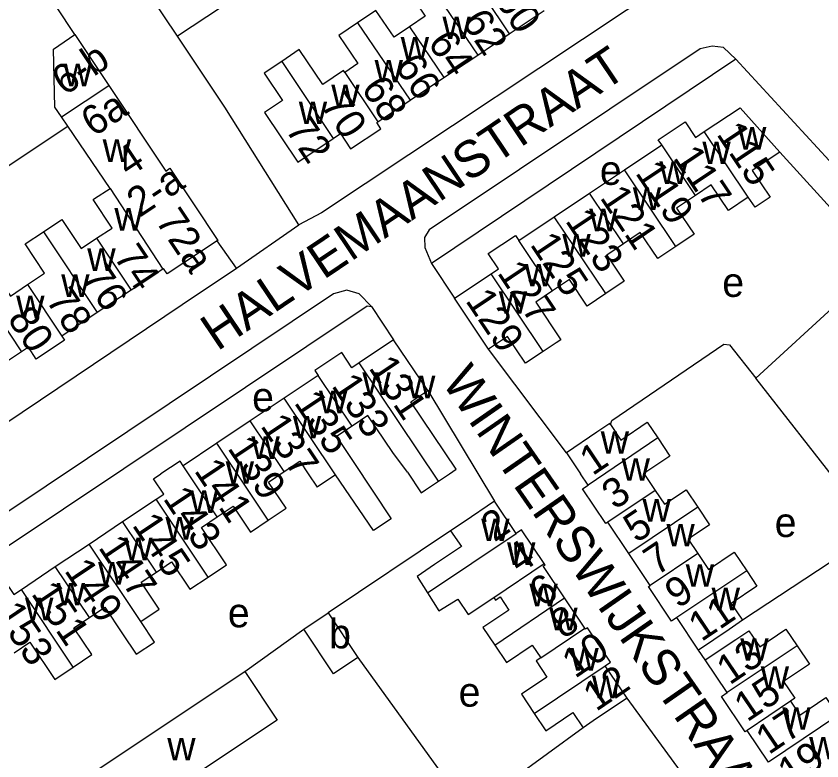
# Model space of a CAD drawing. Extents: x 158356 to 159894, y 383831 to 385260.
# Drawn here: x 158884.2 to 158994, y 384210.9 to 384312.4 of the extents above; entities that cross this region are included whole.
import ezdxf

# ---------------------------------------------------------------- set-up
doc = ezdxf.new("R2010")
doc.units = 0
for name, color, linetype in [('BLT_Basislijn', 7, 'Continuous'), ('BLT_Bebouwing', 7, 'Continuous'), ('BLT_Centroide', 7, 'Continuous'), ('BLT_Huisnummer', 7, 'Continuous'), ('BLT_Huisnummer_ tussenligend', 7, 'Continuous'), ('BLT_Huisnummer_reeks', 7, 'Continuous'), ('BLT_Onderverdeling_panden', 7, 'Continuous'), ('BLT_Straatnaam', 7, 'Continuous'), ('BLT_Vlakafsluiter', 7, 'Continuous')]:
    doc.layers.add(name, color=color, linetype=linetype)

msp = doc.modelspace()

# ---------------------------------------------------------------- linework, layer by layer
at = {"layer": 'BLT_Basislijn'}
for p, q in [((158924.95, 384322.07), (158906.15, 384309.68)), ((159022.47, 384262.77), (158982.28, 384306.54)), ((158988.24, 384293.86), (159002.07, 384278.66)), ((158984.98, 384263.05), (158996.47, 384273.59)), ((158959.16, 384252.88), (158948.56, 384267.02)), ((159001.46, 384241.95), (158984.98, 384263.05)), ((158940.26, 384261.37), (158949.37, 384246.27)), ((158943.39, 384242.25), (158926.68, 384231.06)), ((158915.33, 384223.05), (158923.36, 384228.85)), ((158978.09, 384224.66), (158977.18, 384226)), ((158930.73, 384224.98), (158945.89, 384204.06)), ((158979.18, 384203.45), (158967.44, 384219.43)), ((158961.44, 384215.4), (158945.89, 384204.06))]:
    msp.add_line(p, q, dxfattribs=at)
for points in [[(158959.61, 384341.76), (158973.75, 384319.75), (158974.01, 384318.23), (158973.25, 384317.18), (158925.8, 384285.6), (158922.7, 384283.94)], [(158906.15, 384309.68), (158889.77, 384334.13)], [(158892.18, 384309.89), (158882.19, 384325.03), (158881.31, 384325.78), (158873.9, 384320.84)], [(158922.7, 384283.94), (158912.61, 384300), (158906.15, 384309.68)], [(158982.28, 384306.54), (158980.6, 384308.12), (158979.04, 384308.32), (158977.39, 384307.96), (158940.44, 384283.26), (158939.81, 384282.23), (158939.86, 384280.87), (158940.8, 384278.67)], [(158982.28, 384306.54), (158940.8, 384278.67)], [(158797.78, 384244.29), (158799.68, 384245.48), (158809.98, 384243.39), (158891.2, 384297.39)], [(158914.2, 384278.07), (158911.56, 384281.79)], [(158812.32, 384215.48), (158814.95, 384211.31), (158906.8, 384273.1), (158914.2, 384278.07)], [(158940.8, 384278.67), (158943.92, 384273.95)], [(158932.59, 384272.84), (158930.9, 384274.57), (158929.22, 384275.07), (158927.41, 384274.56), (158849.03, 384222.1), (158848.3, 384220.88), (158848.42, 384219.19), (158849.2, 384217.57)], [(158849.2, 384217.57), (158932, 384272.92), (158932.59, 384272.84)], [(158932.59, 384272.84), (158935.62, 384268.3)], [(158965.16, 384256.75), (158965.34, 384257.27), (158980.61, 384267.7), (158981.38, 384267.6), (158984.98, 384263.05)], [(159001.46, 384241.95), (159000.15, 384241.24), (158983.15, 384230.05)]]:
    msp.add_lwpolyline(points, dxfattribs=at)
at = {"layer": 'BLT_Bebouwing'}
for p, q in [((158951.37, 384309.97), (158956.15, 384313.15)), ((158947.09, 384307.1), (158951.37, 384309.97)), ((158942.47, 384304.02), (158947.09, 384307.1)), ((158937.86, 384300.94), (158942.47, 384304.02)), ((158891.2, 384297.39), (158890.35, 384298.66)), ((158896.99, 384288.89), (158891.2, 384297.39)), ((158967.09, 384291.47), (158972.16, 384294.86)), ((158962.33, 384288.28), (158967.09, 384291.47)), ((158957.51, 384285.05), (158962.33, 384288.28)), ((158952.69, 384281.82), (158957.51, 384285.05)), ((158904.14, 384277.93), (158899.83, 384275.07)), ((158943.92, 384273.95), (158948.91, 384277.29)), ((158899.83, 384275.07), (158895.22, 384272)), ((158948.56, 384267.02), (158943.92, 384273.95)), ((158895.22, 384272), (158890.39, 384268.78)), ((158935.62, 384268.3), (158930.91, 384265.15)), ((158940.26, 384261.37), (158935.62, 384268.3)), ((158884.89, 384266.64), (158879.82, 384263.27)), ((158925.35, 384263.43), (158920.7, 384260.32)), ((158920.7, 384260.32), (158916.07, 384257.22)), ((158916.07, 384257.22), (158911.52, 384254.18)), ((158911.52, 384254.18), (158906.93, 384251.11)), ((158959.16, 384252.88), (158961.1, 384250.01)), ((158918.56, 384248.89), (158920.69, 384250.32)), ((158923.99, 384250), (158925.19, 384248.21)), ((158927.68, 384249.88), (158925.19, 384248.21)), ((158941.72, 384249.01), (158943.24, 384250.03)), ((158962.12, 384248.48), (158961.1, 384250.01)), ((158969.73, 384250.04), (158971.27, 384247.76)), ((158898.68, 384243.5), (158903.24, 384246.55)), ((158952.31, 384241.89), (158949.37, 384246.27)), ((158894.1, 384240.44), (158898.68, 384243.5)), ((158967.69, 384239.14), (158964.81, 384243.42)), ((158889.5, 384237.36), (158894.1, 384240.44)), ((158970.6, 384234.81), (158967.69, 384239.14)), ((158884.88, 384234.26), (158889.5, 384237.36)), ((158958.93, 384233.09), (158956.12, 384237.26)), ((158961.69, 384228.98), (158958.93, 384233.09)), ((158923.36, 384228.85), (158926.68, 384231.06)), ((158926.68, 384231.06), (158930.73, 384224.98)), ((158977.18, 384226), (158974.21, 384230.41)), ((158981.09, 384220.2), (158978.09, 384224.66)), ((158889.79, 384206.08), (158915.33, 384223.05)), ((158967.44, 384219.43), (158964.47, 384223.85)), ((158986.7, 384210.73), (158983.81, 384215.04))]:
    msp.add_line(p, q, dxfattribs=at)
for points in [[(158939.93, 384317.73), (158937.46, 384316.07), (158939.93, 384312.4), (158937.8, 384310.96)], [(158937.8, 384310.96), (158935.67, 384309.53), (158933.21, 384313.18), (158930.69, 384311.47)], [(158930.69, 384311.47), (158928.17, 384309.76), (158930.74, 384305.94), (158928.95, 384304.74)], [(158890.35, 384298.66), (158889.46, 384300), (158889.25, 384307.92), (158892.18, 384309.89)], [(158892.18, 384309.89), (158896.8, 384302.95)], [(158928.95, 384304.74), (158928.78, 384304.99), (158925.95, 384303.1), (158922.76, 384307.84), (158922.14, 384307.43), (158920.37, 384306.24)], [(158920.37, 384306.24), (158917.98, 384304.65), (158920.47, 384300.92), (158919.09, 384300), (158918.03, 384299.29), (158922.56, 384292.5), (158927.39, 384295.73)], [(158896.8, 384302.95), (158904.55, 384291.29), (158905.1, 384291.66), (158911.64, 384281.84), (158911.56, 384281.79)], [(158933.45, 384297.99), (158936.46, 384300), (158937.86, 384300.94)], [(158977.96, 384296.67), (158982.83, 384299.92), (158988.24, 384293.86)], [(158927.39, 384295.73), (158928.38, 384296.39), (158929.76, 384294.31), (158933.87, 384297.06), (158933.31, 384297.9), (158933.45, 384297.99)], [(158972.16, 384294.86), (158971.69, 384295.56), (158975.35, 384298.01), (158976.77, 384295.87), (158977.96, 384296.67)], [(158988.24, 384293.86), (158984.49, 384291.35), (158986.93, 384287.72), (158984.88, 384286.35), (158983.95, 384287.73)], [(158895.14, 384282.12), (158897.25, 384283.52), (158894.66, 384287.42), (158894.86, 384287.55), (158896.99, 384288.89)], [(158983.95, 384287.73), (158981.24, 384285.92), (158978.92, 384289.39), (158976.78, 384287.96)], [(158976.78, 384287.96), (158974.19, 384286.23), (158976.57, 384282.67), (158974.09, 384281.01)], [(158887.9, 384283.01), (158890.4, 384284.68), (158893.03, 384280.72), (158895.14, 384282.12)], [(158885.72, 384275.8), (158888.05, 384277.35), (158885.39, 384281.35), (158887.9, 384283.01)], [(158948.91, 384277.29), (158949.91, 384277.96), (158948.52, 384280.04), (158952.22, 384282.52), (158952.69, 384281.82)], [(158974.09, 384281.01), (158971.62, 384279.35), (158969.24, 384282.89), (158966.96, 384281.36)], [(158911.56, 384281.79), (158904.76, 384277.27), (158904.27, 384278.02), (158904.14, 384277.93)], [(158966.96, 384281.36), (158964.68, 384279.83), (158967.06, 384276.27), (158964.53, 384274.58)], [(158877.59, 384277.6), (158880.06, 384279.24), (158883.39, 384274.25), (158885.72, 384275.8)], [(158964.53, 384274.58), (158962, 384272.88), (158959.58, 384276.49), (158957.28, 384274.95)], [(158957.28, 384274.95), (158954.99, 384273.42), (158958.41, 384268.3), (158957.75, 384267.86), (158956, 384266.69)], [(158890.39, 384268.78), (158890.76, 384268.22), (158886.9, 384265.66), (158885.83, 384267.27), (158884.89, 384266.64)], [(158956, 384266.69), (158953.59, 384265.08), (158951.14, 384268.74), (158948.56, 384267.02)], [(158930.91, 384265.15), (158929.92, 384264.48), (158928.54, 384266.54), (158924.9, 384264.1), (158925.35, 384263.43)], [(158943.24, 384250.03), (158944.14, 384250.63), (158937.98, 384259.84), (158940.26, 384261.37)], [(158937.5, 384250.25), (158935.5, 384252.91), (158932.12, 384257.96), (158929.97, 384256.52)], [(158965.16, 384256.75), (158966.59, 384254.62), (158970.17, 384257.04), (158971.62, 384254.9)], [(158929.97, 384256.52), (158927.82, 384255.09), (158930.18, 384251.55), (158935.3, 384243.9), (158932.88, 384242.28), (158927.68, 384249.88)], [(158965.16, 384256.75), (158965.07, 384256.87), (158963.3, 384255.68), (158959.16, 384252.88)], [(158971.62, 384254.9), (158973.28, 384252.44), (158969.73, 384250.04)], [(158906.93, 384251.11), (158906.51, 384251.75), (158903.89, 384250)], [(158920.69, 384250.32), (158922.82, 384251.74), (158923.99, 384250)], [(158903.24, 384246.55), (158904.28, 384247.25), (158902.89, 384249.33), (158903.89, 384250)], [(158937.5, 384250.25), (158939.38, 384247.44), (158939.98, 384247.85), (158941.72, 384249.01)], [(158918.53, 384243.7), (158920.95, 384245.32), (158918.56, 384248.89)], [(158964.81, 384243.42), (158964.52, 384243.23), (158961.35, 384247.96), (158962.12, 384248.48)], [(158971.27, 384247.76), (158972.54, 384245.86), (158975.49, 384247.84), (158977.09, 384245.46)], [(158949.37, 384246.27), (158945.21, 384243.48), (158943.39, 384242.25)], [(158911.58, 384244.16), (158913.75, 384245.61), (158916.12, 384242.08), (158918.53, 384243.7)], [(158977.09, 384245.46), (158978.69, 384243.08), (158975.76, 384241.11), (158977.07, 384239.16)], [(158910.35, 384235.93), (158912.84, 384237.6), (158909.42, 384242.71), (158911.58, 384244.16)], [(158943.39, 384242.25), (158944.85, 384240.09), (158941.2, 384237.64), (158938.83, 384236.04), (158940.24, 384233.78)], [(158956.15, 384237.78), (158953.05, 384242.39), (158952.31, 384241.89)], [(158977.07, 384239.16), (158978.53, 384236.99), (158982.03, 384239.35), (158983.74, 384236.81)], [(158903.29, 384236.62), (158905.36, 384238.01), (158907.86, 384234.27), (158910.35, 384235.93)], [(158956.12, 384237.26), (158956, 384237.44), (158956.26, 384237.61), (158956.15, 384237.78)], [(158901.18, 384229.87), (158903.68, 384231.55), (158901.21, 384235.23), (158903.29, 384236.62)], [(158983.74, 384236.81), (158985.14, 384234.72), (158981.61, 384232.34), (158983.15, 384230.05)], [(158879.22, 384232.59), (158878.8, 384233.22), (158882.46, 384235.67), (158883.86, 384233.58), (158884.88, 384234.26)], [(158974.21, 384230.41), (158973.51, 384229.93), (158970.35, 384234.64), (158970.6, 384234.81)], [(158940.24, 384233.78), (158941.78, 384231.32), (158944.36, 384232.93), (158945.78, 384230.82), (158949.26, 384233.15)], [(158950.12, 384233.23), (158951.33, 384231.43), (158947.79, 384229.05), (158949.39, 384226.68)], [(158949.26, 384233.15), (158949.49, 384232.8), (158950.12, 384233.23)], [(158894.15, 384230.42), (158896.24, 384231.82), (158898.67, 384228.19), (158900.52, 384225.43), (158903.01, 384227.09), (158901.18, 384229.87)], [(158891.96, 384223.67), (158894.5, 384225.37), (158892.05, 384229.02), (158894.15, 384230.42)], [(158983.15, 384230.05), (158981.33, 384228.79), (158977.18, 384226)], [(158930.73, 384224.98), (158927.41, 384222.77), (158923.36, 384228.85)], [(158964.47, 384223.85), (158965.19, 384224.34), (158962.03, 384229.04), (158961.76, 384228.86), (158961.69, 384228.98)], [(158978.09, 384224.66), (158982.25, 384227.45), (158984.02, 384228.62), (158985.51, 384226.44), (158989.09, 384228.85), (158990.61, 384226.59)], [(158883.91, 384225.62), (158886.04, 384227.05), (158889.43, 384221.98), (158891.96, 384223.67)], [(158949.39, 384226.68), (158950.98, 384224.3), (158954.49, 384226.66), (158955.66, 384224.93)], [(158990.61, 384226.59), (158992.29, 384224.08), (158988.76, 384221.71), (158990.3, 384219.42), (158989.69, 384219.02)], [(158955.66, 384224.93), (158955.03, 384224.51), (158956.51, 384222.31), (158953.03, 384219.97), (158954.79, 384217.35)], [(158915.33, 384223.05), (158919.73, 384216.42), (158894.19, 384199.45)], [(158983.81, 384215.04), (158983.55, 384214.86), (158980.31, 384219.68), (158981.09, 384220.2)], [(158967.44, 384219.43), (158963.29, 384216.65), (158961.44, 384215.4)], [(158989.69, 384219.02), (158990.97, 384217.12), (158994.54, 384219.51), (158996.17, 384217.09)], [(158954.79, 384217.35), (158956.37, 384214.99), (158960.05, 384217.46), (158961.44, 384215.4)]]:
    msp.add_lwpolyline(points, dxfattribs=at)
at = {"layer": 'BLT_Onderverdeling_panden'}
for p, q in [((158939.93, 384317.73), (158947.09, 384307.1)), ((158946.66, 384317.03), (158951.37, 384309.97)), ((158930.69, 384311.47), (158937.86, 384300.94)), ((158937.8, 384310.96), (158942.47, 384304.02)), ((158920.37, 384306.24), (158927.39, 384295.73)), ((158928.95, 384304.74), (158933.45, 384297.99)), ((158890.35, 384298.66), (158896.8, 384302.95)), ((158983.95, 384287.73), (158977.96, 384296.67)), ((158976.78, 384287.96), (158972.16, 384294.86)), ((158974.09, 384281.01), (158967.09, 384291.47)), ((158896.99, 384288.89), (158904.14, 384277.93)), ((158966.96, 384281.36), (158962.33, 384288.28)), ((158964.53, 384274.58), (158957.51, 384285.05)), ((158887.9, 384283.01), (158895.22, 384272)), ((158895.14, 384282.12), (158899.83, 384275.07)), ((158957.28, 384274.95), (158952.69, 384281.82)), ((158877.59, 384277.6), (158884.89, 384266.64)), ((158956, 384266.69), (158948.91, 384277.29)), ((158885.72, 384275.8), (158890.39, 384268.78)), ((158941.72, 384249.01), (158930.91, 384265.15)), ((158929.97, 384256.52), (158925.35, 384263.43)), ((158927.68, 384249.88), (158920.7, 384260.32)), ((158920.69, 384250.32), (158916.07, 384257.22)), ((158971.62, 384254.9), (158962.12, 384248.48)), ((158918.53, 384243.7), (158911.52, 384254.18)), ((158911.58, 384244.16), (158906.93, 384251.11)), ((158971.27, 384247.76), (158964.81, 384243.42)), ((158910.35, 384235.93), (158903.24, 384246.55)), ((158977.09, 384245.46), (158967.69, 384239.14)), ((158903.29, 384236.62), (158898.68, 384243.5)), ((158940.24, 384233.78), (158952.31, 384241.89)), ((158901.18, 384229.87), (158894.1, 384240.44)), ((158977.07, 384239.16), (158970.6, 384234.81)), ((158894.15, 384230.42), (158889.5, 384237.36)), ((158949.26, 384233.15), (158956.15, 384237.78)), ((158983.74, 384236.81), (158974.21, 384230.41)), ((158891.96, 384223.67), (158884.88, 384234.26)), ((158949.39, 384226.68), (158958.93, 384233.09)), ((158955.66, 384224.93), (158961.69, 384228.98)), ((158990.61, 384226.59), (158981.09, 384220.2)), ((158954.79, 384217.35), (158964.47, 384223.85)), ((158989.69, 384219.02), (158983.81, 384215.04)), ((158996.17, 384217.09), (158986.7, 384210.73))]:
    msp.add_line(p, q, dxfattribs=at)
at = {"layer": 'BLT_Vlakafsluiter'}
msp.add_line((158914.2, 384278.07), (158922.7, 384283.94), dxfattribs=at)

# ---------------------------------------------------------------- texts
at = {"layer": 'BLT_Centroide'}
for s, p in [('w', (158942.27, 384309.28)), ('w', (158936.58, 384306.48)), ('w', (158933.02, 384303.36)), ('w', (158890.63, 384302.85)), ('w', (158927.12, 384300)), ('w', (158922.69, 384297.69)), ('w', (158982.55, 384294.2)), ('w', (158895.96, 384292.52)), ('w', (158977.7, 384292.23)), ('e', (158963.73, 384289.4)), ('w', (158971.83, 384289.52)), ('w', (158968.22, 384285.98)), ('w', (158897.56, 384283.17)), ('w', (158962.28, 384283.09)), ('w', (158958.61, 384279.62)), ('w', (158893.86, 384277.66)), ('w', (158953.47, 384275.56)), ('w', (158890.31, 384274.14)), ('e', (158980.41, 384274.13)), ('w', (158949.95, 384271.84)), ('w', (158884.17, 384271.23)), ('w', (158931.36, 384260.78)), ('w', (158937.44, 384260.31)), ('e', (158916.33, 384258.5)), ('w', (158925.44, 384258.27)), ('w', (158921.88, 384254.84)), ('w', (158963.84, 384252.75)), ('w', (158916.23, 384252.05)), ('w', (158912.73, 384248.66)), ('w', (158966.69, 384249.06)), ('w', (158907.86, 384244.69)), ('w', (158969.54, 384243.5)), ('w', (158904.52, 384241.05)), ('w', (158947.55, 384240.84)), ('e', (158987.56, 384241.4)), ('w', (158972.8, 384240.12)), ('w', (158898.89, 384238.23)), ('w', (158951.08, 384237.59)), ('w', (158895.34, 384234.91)), ('w', (158975.43, 384234.62)), ('w', (158889.69, 384232.08)), ('w', (158954.12, 384231.97)), ('w', (158978.96, 384231.41)), ('w', (158885.38, 384230.05)), ('e', (158913.02, 384229.09)), ('w', (158956.83, 384228.69)), ('b', (158926.82, 384226.22)), ('w', (158982.86, 384224.53)), ('w', (158959.7, 384223.19)), ('w', (158985.65, 384220.72)), ('w', (158962.65, 384219.41)), ('e', (158944.48, 384218.28)), ('w', (158988.59, 384215.12)), ('w', (158992.25, 384211.09)), ('w', (158904.76, 384210.95))]:
    msp.add_text(s, height=4, dxfattribs=at).set_placement(p)
at = {"layer": 'BLT_Huisnummer'}
for s, rotation, p in [('60', 303.7498, (158949.31, 384314.64)), ('64', 303.7498, (158940.18, 384308.79)), ('68', 303.7498, (158931.1, 384302.56)), ('72', 303.7498, (158920.78, 384296.96)), ('115', 303.8062, (158979.53, 384296.32)), ('119', 303.8062, (158968.47, 384291.03)), ('123', 303.8062, (158958.92, 384284.51)), ('74', 303.6373, (158897.38, 384279.61)), ('78', 303.6373, (158888.13, 384273.69)), ('129', 303.8062, (158945.32, 384273.62)), ('131', 303.7951, (158932.12, 384264.46)), ('135', 303.7951, (158921.96, 384259.71)), ('139', 303.7951, (158912.89, 384253.52)), ('1', 33.8842, (158962.73, 384249.68)), ('143', 303.7951, (158904.1, 384246.65)), ('2', 33.8989, (158949.33, 384240.64)), ('5', 33.8842, (158968.71, 384240.5)), ('147', 303.7951, (158895.28, 384239.99)), ('6', 33.8989, (158955.88, 384231.73)), ('151', 303.7951, (158886.13, 384233.68)), ('11', 33.8842, (158977.56, 384227.05)), ('13', 34.1084, (158981.41, 384221.14)), ('12', 33.8989, (158963.21, 384217.54)), ('17', 34.1084, (158986.75, 384211.64))]:
    msp.add_text(s, height=4, rotation=rotation, dxfattribs=at).set_placement(p)
at = {"layer": 'BLT_Huisnummer_ tussenligend'}
for s, rotation, p in [('62', 303.7498, (158944.79, 384311.67)), ('66', 303.7498, (158935.66, 384305.6)), ('70', 303.7498, (158925.58, 384300.3)), ('117', 303.8062, (158973.62, 384293.1)), ('121', 303.8062, (158963.64, 384287.67)), ('125', 303.8062, (158954.12, 384281.28)), ('76', 303.6373, (158893.02, 384276.81)), ('127', 303.8062, (158949.65, 384277.42)), ('80', 303.6373, (158882.89, 384271.14)), ('133', 303.7951, (158927.07, 384262.03)), ('137', 303.7951, (158917.38, 384256.55)), ('141', 303.7951, (158908.34, 384250.45)), ('3', 33.8842, (158965.75, 384245.03)), ('145', 303.7951, (158899.88, 384243.02)), ('4', 33.8989, (158952.77, 384236.29)), ('7', 33.8842, (158971.45, 384236.04)), ('149', 303.7951, (158890.65, 384236.82)), ('9', 33.8842, (158974.35, 384231.56)), ('153', 303.7951, (158881.2, 384230.94)), ('8', 33.8989, (158958.75, 384227.4)), ('10', 33.8989, (158960.34, 384222.05)), ('15', 34.1084, (158983.81, 384216.1)), ('19', 34.1084, (158989.75, 384207.19))]:
    msp.add_text(s, height=4, rotation=rotation, dxfattribs=at).set_placement(p)
at = {"layer": 'BLT_Huisnummer_reeks'}
for s, rotation, p in [('6-b', 33.6121, (158890.77, 384301.47)), ('6a', 33.6336, (158894.74, 384295.86)), ('4', 33.6336, (158899.5, 384290.37)), ('2-a', 33.6336, (158900.99, 384284.89)), ('72a', 303.7498, (158903.06, 384284.5))]:
    msp.add_text(s, height=4, rotation=rotation, dxfattribs=at).set_placement(p)
at = {"layer": 'BLT_Straatnaam'}
for s, height, rotation, p in [('HALVEMAANSTRAAT', 4.9999, 33.9266, (158911.58, 384266.66)), ('WINTERSWIJKSTRAAT', 5, 304.7971, (158942.06, 384262.55))]:
    msp.add_text(s, height=height, rotation=rotation, dxfattribs=at).set_placement(p)

doc.saveas('drawing.dxf')
